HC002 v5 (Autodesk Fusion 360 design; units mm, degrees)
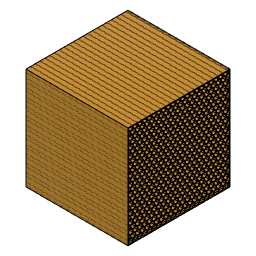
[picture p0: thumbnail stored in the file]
sketch "Sketch1" plane through (0, 0, 0) normal (1, 0, 0) x axis (0, 0, -1)
  line L1 (-75, 75) -> (75, 75)
  line L2 (-75, -75) -> (-75, 75)
  line L3 (75, -75) -> (-75, -75)
  line L4 (75, 75) -> (75, -75)
  line L5 (-75, -75) -> (75, 75)
  line L6 (75, -75) -> (-75, 75)
  line L7 (-71.3532, -71.3532) -> (0, 0)
  line L8 (-68.3532, -69.6211) -> (-68.3532, -73.0852)
  line L9 (-71.3532, -67.8891) -> (-68.3532, -69.6211)
  line L10 (-74, -69.4172) -> (-71.3532, -67.8891)
  line L11 (-72.7687, -74) -> (-74, -73.2891)
  line L12 (-68.3532, -73.0852) -> (-69.9376, -74)
  line L13 (-67.7706, -68.8181) -> (-70.7706, -67.0861)
  line L14 (-64.7706, -67.0861) -> (-67.7706, -68.8181)
  line L15 (-70.7706, -67.0861) -> (-70.7706, -63.622)
  line L16 (-64.7706, -63.622) -> (-64.7706, -67.0861)
  line L17 (-67.7706, -61.8899) -> (-64.7706, -63.622)
  line L18 (-70.7706, -63.622) -> (-67.7706, -61.8899)
  line L19 (-71.3532, -79.3958) -> (-71.3532, -71.3532)
  line L20 (-67.3532, -73.0852) -> (-67.3532, -69.6211)
  line L21 (-65.7687, -74) -> (-67.3532, -73.0852)
  line L22 (-61.3532, -73.0852) -> (-62.9376, -74)
  line L23 (-61.3532, -69.6211) -> (-61.3532, -73.0852)
  line L24 (-64.3532, -67.8891) -> (-61.3532, -69.6211)
  line L25 (-67.3532, -69.6211) -> (-64.3532, -67.8891)
  line L26 (-57.7706, -63.622) -> (-57.7706, -67.0861)
  line L27 (-60.7706, -61.8899) -> (-57.7706, -63.622)
  line L28 (-63.7706, -63.622) -> (-60.7706, -61.8899)
  line L29 (-63.7706, -67.0861) -> (-63.7706, -63.622)
  line L30 (-60.7706, -68.8181) -> (-63.7706, -67.0861)
  line L31 (-57.7706, -67.0861) -> (-60.7706, -68.8181)
  line L32 (-50.3532, -67.8891) -> (-47.3532, -69.6211)
  line L33 (-53.3532, -69.6211) -> (-50.3532, -67.8891)
  line L34 (-51.7687, -74) -> (-53.3532, -73.0852)
  line L35 (-47.3532, -73.0852) -> (-48.9376, -74)
  line L36 (-47.3532, -69.6211) -> (-47.3532, -73.0852)
  line L37 (-53.3532, -73.0852) -> (-53.3532, -69.6211)
  line L38 (-54.3532, -73.0852) -> (-55.9376, -74)
  line L39 (-57.3532, -67.8891) -> (-54.3532, -69.6211)
  line L40 (-60.3532, -69.6211) -> (-57.3532, -67.8891)
  line L41 (-58.7687, -74) -> (-60.3532, -73.0852)
  line L42 (-60.3532, -73.0852) -> (-60.3532, -69.6211)
  line L43 (-54.3532, -69.6211) -> (-54.3532, -73.0852)
  line L44 (-36.3532, -67.8891) -> (-33.3532, -69.6211)
  line L45 (-39.3532, -69.6211) -> (-36.3532, -67.8891)
  line L46 (-37.7687, -74) -> (-39.3532, -73.0852)
  line L47 (-33.3532, -73.0852) -> (-34.9376, -74)
  line L48 (-33.3532, -69.6211) -> (-33.3532, -73.0852)
  line L49 (-39.3532, -73.0852) -> (-39.3532, -69.6211)
  line L50 (-40.3532, -73.0852) -> (-41.9376, -74)
  line L51 (-43.3532, -67.8891) -> (-40.3532, -69.6211)
  line L52 (-46.3532, -69.6211) -> (-43.3532, -67.8891)
  line L53 (-44.7687, -74) -> (-46.3532, -73.0852)
  line L54 (-46.3532, -73.0852) -> (-46.3532, -69.6211)
  line L55 (-40.3532, -69.6211) -> (-40.3532, -73.0852)
  line L56 (-53.7706, -61.8899) -> (-50.7706, -63.622)
  line L57 (-56.7706, -63.622) -> (-53.7706, -61.8899)
  line L58 (-56.7706, -67.0861) -> (-56.7706, -63.622)
  line L59 (-53.7706, -68.8181) -> (-56.7706, -67.0861)
  line L60 (-50.7706, -67.0861) -> (-53.7706, -68.8181)
  line L61 (-50.7706, -63.622) -> (-50.7706, -67.0861)
  line L62 (-49.7706, -67.0861) -> (-49.7706, -63.622)
  line L63 (-46.7706, -68.8181) -> (-49.7706, -67.0861)
  line L64 (-43.7706, -67.0861) -> (-46.7706, -68.8181)
  line L65 (-43.7706, -63.622) -> (-43.7706, -67.0861)
  line L66 (-46.7706, -61.8899) -> (-43.7706, -63.622)
  line L67 (-49.7706, -63.622) -> (-46.7706, -61.8899)
  line L68 (-39.7706, -61.8899) -> (-36.7706, -63.622)
  line L69 (-42.7706, -63.622) -> (-39.7706, -61.8899)
  line L70 (-42.7706, -67.0861) -> (-42.7706, -63.622)
  line L71 (-39.7706, -68.8181) -> (-42.7706, -67.0861)
  line L72 (-36.7706, -67.0861) -> (-39.7706, -68.8181)
  line L73 (-36.7706, -63.622) -> (-36.7706, -67.0861)
  line L74 (-35.7706, -67.0861) -> (-35.7706, -63.622)
  line L75 (-32.7706, -68.8181) -> (-35.7706, -67.0861)
  line L76 (-29.7706, -67.0861) -> (-32.7706, -68.8181)
  line L77 (-29.7706, -63.622) -> (-29.7706, -67.0861)
  line L78 (-32.7706, -61.8899) -> (-29.7706, -63.622)
  line L79 (-35.7706, -63.622) -> (-32.7706, -61.8899)
  line L80 (9.2294, -61.8899) -> (12.2294, -63.622)
  line L81 (12.2294, -63.622) -> (12.2294, -67.0861)
  line L82 (-0.7706, -63.622) -> (2.2294, -61.8899)
  line L83 (2.6468, -73.0852) -> (2.6468, -69.6211)
  line L84 (-4.3532, -69.6211) -> (-1.3532, -67.8891)
  line L85 (1.6468, -69.6211) -> (1.6468, -73.0852)
  line L86 (-14.7706, -63.622) -> (-11.7706, -61.8899)
  line L87 (-25.7706, -61.8899) -> (-22.7706, -63.622)
  line L88 (-5.3532, -73.0852) -> (-6.9376, -74)
  line L89 (-2.7687, -74) -> (-4.3532, -73.0852)
  line L90 (-7.7706, -63.622) -> (-4.7706, -61.8899)
  line L91 (-0.7706, -67.0861) -> (-0.7706, -63.622)
  line L92 (5.2294, -67.0861) -> (2.2294, -68.8181)
  line L93 (-8.3532, -67.8891) -> (-5.3532, -69.6211)
  line L94 (2.2294, -68.8181) -> (-0.7706, -67.0861)
  line L95 (2.6468, -69.6211) -> (5.6468, -67.8891)
  line L96 (-4.7706, -61.8899) -> (-1.7706, -63.622)
  line L97 (8.6468, -69.6211) -> (8.6468, -73.0852)
  line L98 (-21.7706, -63.622) -> (-18.7706, -61.8899)
  line L99 (1.6468, -73.0852) -> (0.0624, -74)
  line L100 (-7.7706, -67.0861) -> (-7.7706, -63.622)
  line L101 (-18.7706, -61.8899) -> (-15.7706, -63.622)
  line L102 (5.2294, -63.622) -> (5.2294, -67.0861)
  line L103 (4.2313, -74) -> (2.6468, -73.0852)
  line L104 (-28.7706, -63.622) -> (-25.7706, -61.8899)
  line L105 (2.2294, -61.8899) -> (5.2294, -63.622)
  line L106 (6.2294, -63.622) -> (9.2294, -61.8899)
  line L107 (-11.7706, -61.8899) -> (-8.7706, -63.622)
  line L108 (12.2294, -67.0861) -> (9.2294, -68.8181)
  line L109 (-1.3532, -67.8891) -> (1.6468, -69.6211)
  line L110 (-8.7706, -67.0861) -> (-11.7706, -68.8181)
  line L111 (-11.3532, -69.6211) -> (-8.3532, -67.8891)
  line L112 (-9.7687, -74) -> (-11.3532, -73.0852)
  line L113 (-1.7706, -63.622) -> (-1.7706, -67.0861)
  line L114 (8.6468, -73.0852) -> (7.0624, -74)
  line L115 (-1.7706, -67.0861) -> (-4.7706, -68.8181)
  line L116 (5.6468, -67.8891) -> (8.6468, -69.6211)
  line L117 (-4.7706, -68.8181) -> (-7.7706, -67.0861)
  line L118 (-11.7706, -68.8181) -> (-14.7706, -67.0861)
  line L119 (6.2294, -67.0861) -> (6.2294, -63.622)
  line L120 (-8.7706, -63.622) -> (-8.7706, -67.0861)
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  point P6 (0, 0)
  point P1 (0, 0)
  point P7 (0, 0)
  point P8 (-71.3532, -71.3532)
  point P12 (-71.3532, -71.3532)
  point P3957 (0, 0)
  point P3958 (-75, 21.9776)
  point P3971 (-75, 45.9776)
  point P3981 (-74.3532, 74.3532)
  point P3982 (-75, 63.3143)
  point P3998 (75, 56.5105)
  point P4 (-75, -75)
  point P5 (75, -75)
  point P3 (-75, 75)
  point P15 (-67.8532, -65.291)
  point P26 (-64.3532, -71.3532)
  point P3955 (-74, -74)
  point P3956 (74, -74)
  point P3954 (-74, 74)
  horizontal L1
  perpendicular L1 L2
  parallel L1 L3
  parallel L2 L4
  coincident L5 P6
  coincident L6 P6
  coincident P1 P6
  coincident P6 P7
  vertical L8
  coincident P8 P12
  vertical L19
  coincident P6 P3957
  coincident L2 P3958
  coincident L2 P3971
  coincident L6 P3981
  coincident L2 P3982
  coincident L4 P3998
  dimension "d1" distance P4 P5 = 150
  dimension "d2" distance P3 P4 = 150
  dimension "d10" distance P12 P15 = 7
  dimension "d15" distance P15 P26 = 7
  dimension "d56" distance P3955 P3956 = 148
  dimension "d57" distance P3954 P3955 = 148
  dimension "d58" distance P12 L8 = 3
  dimension "d18" R-Pattern2-uDistance = 7
  dimension "d19" R-Pattern2-vDistance = 0
  dimension "d26" R-Pattern4-uDistance = 14
  dimension "d27" R-Pattern4-vDistance = 0
extrude "Extrude1" new body sketch "Sketch1" along normal blind 150
sketch "Sketch2" plane through (150, 0, 0) normal (1, 0, 0) x axis (0, 0, -1)
  line L1 (9.2294, -44.8181) -> (12.2294, -43.0861)
  line L2 (6.2294, -43.0861) -> (9.2294, -44.8181)
  line L3 (6.2294, -39.622) -> (6.2294, -43.0861)
  line L4 (9.2294, -37.8899) -> (6.2294, -39.622)
  line L5 (12.2294, -39.622) -> (9.2294, -37.8899)
  line L6 (12.2294, -43.0861) -> (12.2294, -39.622)
  line L7 (-49.7706, 32.378) -> (-49.7706, 28.9139)
  line L8 (-46.7706, 34.1101) -> (-49.7706, 32.378)
  line L9 (-43.7706, 32.378) -> (-46.7706, 34.1101)
  line L10 (-43.7706, 28.9139) -> (-43.7706, 32.378)
  line L11 (-46.7706, 27.1819) -> (-43.7706, 28.9139)
  line L12 (-49.7706, 28.9139) -> (-46.7706, 27.1819)
  line L13 (-50.7706, 28.9139) -> (-50.7706, 32.378)
  line L14 (-53.7706, 27.1819) -> (-50.7706, 28.9139)
  line L15 (-56.7706, 28.9139) -> (-53.7706, 27.1819)
  line L16 (-56.7706, 32.378) -> (-56.7706, 28.9139)
  line L17 (-53.7706, 34.1101) -> (-56.7706, 32.378)
  line L18 (-50.7706, 32.378) -> (-53.7706, 34.1101)
  line L19 (13.2294, 32.378) -> (13.2294, 28.9139)
  line L20 (16.2294, 34.1101) -> (13.2294, 32.378)
  line L21 (19.2294, 32.378) -> (16.2294, 34.1101)
  line L22 (19.2294, 28.9139) -> (19.2294, 32.378)
  line L23 (16.2294, 27.1819) -> (19.2294, 28.9139)
  line L24 (13.2294, 28.9139) -> (16.2294, 27.1819)
  line L25 (-25.3532, 58.9148) -> (-22.3532, 57.1827)
  line L26 (-25.3532, 62.3789) -> (-25.3532, 58.9148)
  line L27 (-22.3532, 64.1109) -> (-25.3532, 62.3789)
  line L28 (-19.3532, 62.3789) -> (-22.3532, 64.1109)
  line L29 (-19.3532, 58.9148) -> (-19.3532, 62.3789)
  line L30 (-22.3532, 57.1827) -> (-19.3532, 58.9148)
  line L31 (27.2294, 32.378) -> (27.2294, 28.9139)
  line L32 (30.2294, 34.1101) -> (27.2294, 32.378)
  line L33 (33.2294, 32.378) -> (30.2294, 34.1101)
  line L34 (33.2294, 28.9139) -> (33.2294, 32.378)
  line L35 (30.2294, 27.1819) -> (33.2294, 28.9139)
  line L36 (27.2294, 28.9139) -> (30.2294, 27.1819)
  line L37 (12.6468, 21.1827) -> (15.6468, 22.9148)
  line L38 (9.6468, 22.9148) -> (12.6468, 21.1827)
  line L39 (9.6468, 26.3789) -> (9.6468, 22.9148)
  line L40 (12.6468, 28.1109) -> (9.6468, 26.3789)
  line L41 (15.6468, 26.3789) -> (12.6468, 28.1109)
  line L42 (15.6468, 22.9148) -> (15.6468, 26.3789)
  line L43 (16.6468, 26.3789) -> (16.6468, 22.9148)
  line L44 (19.6468, 28.1109) -> (16.6468, 26.3789)
  line L45 (22.6468, 26.3789) -> (19.6468, 28.1109)
  line L46 (22.6468, 22.9148) -> (22.6468, 26.3789)
  line L47 (19.6468, 21.1827) -> (22.6468, 22.9148)
  line L48 (16.6468, 22.9148) -> (19.6468, 21.1827)
  line L49 (29.6468, 26.3789) -> (26.6468, 28.1109)
  line L50 (29.6468, 22.9148) -> (29.6468, 26.3789)
  line L51 (26.6468, 21.1827) -> (29.6468, 22.9148)
  line L52 (23.6468, 22.9148) -> (26.6468, 21.1827)
  line L53 (23.6468, 26.3789) -> (23.6468, 22.9148)
  line L54 (26.6468, 28.1109) -> (23.6468, 26.3789)
  line L55 (20.2294, 32.378) -> (20.2294, 28.9139)
  line L56 (23.2294, 34.1101) -> (20.2294, 32.378)
  line L57 (26.2294, 32.378) -> (23.2294, 34.1101)
  line L58 (26.2294, 28.9139) -> (26.2294, 32.378)
  line L59 (23.2294, 27.1819) -> (26.2294, 28.9139)
  line L60 (20.2294, 28.9139) -> (23.2294, 27.1819)
  line L61 (9.2294, 27.1819) -> (12.2294, 28.9139)
  line L62 (6.2294, 28.9139) -> (9.2294, 27.1819)
  line L63 (6.2294, 32.378) -> (6.2294, 28.9139)
  line L64 (9.2294, 34.1101) -> (6.2294, 32.378)
  line L65 (12.2294, 32.378) -> (9.2294, 34.1101)
  line L66 (12.2294, 28.9139) -> (12.2294, 32.378)
  line L67 (-61.3532, 26.3789) -> (-64.3532, 28.1109)
  line L68 (-61.3532, 22.9148) -> (-61.3532, 26.3789)
  line L69 (-64.3532, 21.1827) -> (-61.3532, 22.9148)
  line L70 (-67.3532, 22.9148) -> (-64.3532, 21.1827)
  line L71 (-67.3532, 26.3789) -> (-67.3532, 22.9148)
  line L72 (-64.3532, 28.1109) -> (-67.3532, 26.3789)
  line L73 (5.2294, 32.378) -> (2.2294, 34.1101)
  line L74 (5.2294, 28.9139) -> (5.2294, 32.378)
  line L75 (2.2294, 27.1819) -> (5.2294, 28.9139)
  line L76 (-0.7706, 28.9139) -> (2.2294, 27.1819)
  line L77 (-0.7706, 32.378) -> (-0.7706, 28.9139)
  line L78 (2.2294, 34.1101) -> (-0.7706, 32.378)
  line L79 (-15.7706, 32.378) -> (-18.7706, 34.1101)
  line L80 (-15.7706, 28.9139) -> (-15.7706, 32.378)
  line L81 (-18.7706, 27.1819) -> (-15.7706, 28.9139)
  line L82 (-21.7706, 28.9139) -> (-18.7706, 27.1819)
  line L83 (-21.7706, 32.378) -> (-21.7706, 28.9139)
  line L84 (-18.7706, 34.1101) -> (-21.7706, 32.378)
  line L85 (-4.7706, 34.1101) -> (-7.7706, 32.378)
  line L86 (-1.7706, 32.378) -> (-4.7706, 34.1101)
  line L87 (-1.7706, 28.9139) -> (-1.7706, 32.378)
  line L88 (-4.7706, 27.1819) -> (-1.7706, 28.9139)
  line L89 (-7.7706, 28.9139) -> (-4.7706, 27.1819)
  line L90 (-7.7706, 32.378) -> (-7.7706, 28.9139)
  line L91 (54.2294, 28.9139) -> (54.2294, 32.378)
  line L92 (51.2294, 27.1819) -> (54.2294, 28.9139)
  line L93 (48.2294, 28.9139) -> (51.2294, 27.1819)
  line L94 (48.2294, 32.378) -> (48.2294, 28.9139)
  line L95 (51.2294, 34.1101) -> (48.2294, 32.378)
  line L96 (54.2294, 32.378) -> (51.2294, 34.1101)
  line L97 (-4.7706, 22.1101) -> (-7.7706, 20.378)
  line L98 (-1.7706, 20.378) -> (-4.7706, 22.1101)
  line L99 (-1.7706, 16.9139) -> (-1.7706, 20.378)
  line L100 (-4.7706, 15.1819) -> (-1.7706, 16.9139)
  line L101 (-7.7706, 16.9139) -> (-4.7706, 15.1819)
  line L102 (-7.7706, 20.378) -> (-7.7706, 16.9139)
  line L103 (-8.3532, 64.1109) -> (-11.3532, 62.3789)
  line L104 (-5.3532, 62.3789) -> (-8.3532, 64.1109)
  line L105 (-5.3532, 58.9148) -> (-5.3532, 62.3789)
  line L106 (-8.3532, 57.1827) -> (-5.3532, 58.9148)
  line L107 (-11.3532, 58.9148) -> (-8.3532, 57.1827)
  line L108 (-11.3532, 62.3789) -> (-11.3532, 58.9148)
  line L109 (74, 10.1335) -> (74, 15.1601)
  line L110 (72.6468, 10.9148) -> (74, 10.1335)
  line L111 (72.6468, 14.3789) -> (72.6468, 10.9148)
  line L112 (74, 15.1601) -> (72.6468, 14.3789)
  line L113 (-35.7706, 68.378) -> (-35.7706, 64.9139)
  line L114 (-32.7706, 70.1101) -> (-35.7706, 68.378)
  line L115 (-29.7706, 68.378) -> (-32.7706, 70.1101)
  line L116 (-29.7706, 64.9139) -> (-29.7706, 68.378)
  line L117 (-32.7706, 63.1819) -> (-29.7706, 64.9139)
  line L118 (-35.7706, 64.9139) -> (-32.7706, 63.1819)
  line L119 (13.2294, 68.378) -> (13.2294, 64.9139)
  line L120 (16.2294, 70.1101) -> (13.2294, 68.378)
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  point P1904 (-28.7706, 8.378)
  point P3256 (-28.7706, 8.378)
  point P1905 (-25.7706, 10.1101)
  point P3257 (-25.7706, 10.1101)
  point P1906 (-22.7706, 8.378)
  point P3258 (-22.7706, 8.378)
  point P1907 (-22.7706, 4.9139)
  point P3259 (-22.7706, 4.9139)
  point P1908 (-25.7706, 3.1819)
  point P3260 (-25.7706, 3.1819)
  point P1909 (-28.7706, 4.9139)
  point P3261 (-28.7706, 4.9139)
  point P3262 (-28.7706, 4.9139)
  point P1429 (-25.7706, -13.8899)
  point P3263 (-25.7706, -13.8899)
  point P1430 (-22.7706, -15.622)
  point P3264 (-22.7706, -15.622)
  point P3265 (-22.7706, -15.622)
  point P1431 (-22.7706, -19.0861)
  point P3266 (-22.7706, -19.0861)
  point P3267 (-22.7706, -19.0861)
  point P1432 (-25.7706, -20.8181)
  point P3268 (-25.7706, -20.8181)
  point P1433 (-28.7706, -19.0861)
  point P3269 (-28.7706, -19.0861)
  point P1428 (-28.7706, -15.622)
  point P3270 (-28.7706, -15.622)
  coincident P1904 P3256
  coincident P1905 P3257
  coincident P1906 P3258
  coincident P1907 P3259
  coincident P1908 P3260
  coincident P1909 P3261
  coincident P1909 P3262
  coincident P1429 P3263
  coincident P1430 P3264
  coincident P1430 P3265
  coincident P1431 P3266
  coincident P1431 P3267
  coincident P1432 P3268
  coincident P1433 P3269
  coincident P1428 P3270
  dimension "d61" diameter = 23.5
extrude "Extrude2" new body sketch "Sketch2" along normal blind 20
sketch "Sketch3" plane through (170, 0, 0) normal (1, 0, 0) x axis (0, 0, -1)
  line L1 (-21.7706, -7.0861) -> (-21.7706, -3.622)
  line L2 (-18.7706, -8.8181) -> (-21.7706, -7.0861)
  line L3 (-15.7706, -7.0861) -> (-18.7706, -8.8181)
  line L4 (-15.7706, -3.622) -> (-15.7706, -7.0861)
  line L5 (-18.7706, -1.8899) -> (-15.7706, -3.622)
  line L6 (-21.7706, -3.622) -> (-18.7706, -1.8899)
  line L7 (-28.7706, 4.9139) -> (-28.7706, 8.378)
  line L8 (-25.7706, 3.1819) -> (-28.7706, 4.9139)
  line L9 (-22.7706, 4.9139) -> (-25.7706, 3.1819)
  line L10 (-22.7706, 8.378) -> (-22.7706, 4.9139)
  line L11 (-25.7706, 10.1101) -> (-22.7706, 8.378)
  line L12 (-28.7706, 8.378) -> (-25.7706, 10.1101)
  line L13 (-29.7706, -7.0861) -> (-32.7706, -8.8181)
  line L14 (-29.7706, -3.622) -> (-29.7706, -7.0861)
  line L15 (-32.7706, -1.8899) -> (-29.7706, -3.622)
  line L16 (-35.7706, -3.622) -> (-32.7706, -1.8899)
  line L17 (-35.7706, -7.0861) -> (-35.7706, -3.622)
  line L18 (-32.7706, -8.8181) -> (-35.7706, -7.0861)
  line L19 (-25.7706, -13.8899) -> (-22.7706, -15.622)
  line L20 (-28.7706, -15.622) -> (-25.7706, -13.8899)
  line L21 (-28.7706, -19.0861) -> (-28.7706, -15.622)
  line L22 (-25.7706, -20.8181) -> (-28.7706, -19.0861)
  line L23 (-22.7706, -19.0861) -> (-25.7706, -20.8181)
  line L24 (-22.7706, -15.622) -> (-22.7706, -19.0861)
  line L25 (-15.7706, -5.354) -> (-35.7706, -5.354)
  line L26 (-25.7706, -13.8899) -> (-25.7706, 3.1819)
  circle C1 centre (-25.7706, -5.354) radius 12
  circle C2 centre (-25.7706, -5.354) radius 16
  circle C3 centre (-25.7706, -5.354) radius 4
  point P26 (-35.7706, -5.354)
  point P27 (-15.7706, -5.354)
  point P10 (-25.7706, 3.1819)
  point P28 (-25.7706, 3.1819)
  point P21 (-25.7706, -13.8899)
  point P29 (-25.7706, -13.8899)
  point P30 (-25.7706, -5.354)
  midpoint L17 P26
  midpoint L4 P27
  coincident P10 P28
  coincident P21 P29
  midpoint L25 P30
  concentric C1 C2
  concentric C1 C3
  tangent L14 C3
  dimension "d64" diameter C1 = 24
  dimension "d65" diameter C2 = 32
extrude "Extrude3" add sketch "Sketch3" profile of L1 L2 L3 L4 L5 L6 L7 L8 L9 L10 L11 L12 L13 L14 L15 L16 L17 L18 L19 L20 L21 L22 L23 L24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 along normal blind 8
sketch "Sketch4" plane through (178, 0, 0) normal (1, 0, 0) x axis (0, 0, -1)
  circle C1 centre (-25.7706, -5.354) radius 4
  circle C2 centre (-25.7706, -5.354) radius 16
  circle C3 centre (-25.7706, -5.354) radius 12
  concentric C1 C3
  dimension "d68" diameter C3 = 24
extrude "Extrude4" cut sketch "Sketch4" profile of C1 C3 against normal blind 6.5
fillet "Fillet1" radius 1 0.8
fillet "Fillet2" radius 0.5
fillet "Fillet3" radius 0.5
sketch "Sketch5" plane through (178, 0, 0) normal (1, 0, 0) x axis (0, 0, -1)
  line L1 (-25.7706, 9.846) -> (-25.7706, -5.354)
  line L2 (-24.2706, 6.146) -> (-27.2706, 6.146)
  line L3 (-24.2706, 11.146) -> (-24.2706, 6.146)
  line L4 (-27.2706, 11.146) -> (-24.2706, 11.146)
  line L5 (-27.2706, 6.146) -> (-27.2706, 11.146)
  circle C1 centre (-25.7706, -5.354) radius 13
  circle C2 centre (-25.7706, -5.354) radius 15.2
  point P2 (-25.7706, -5.354)
  point P3 (-25.7706, -5.354)
  point P4 (-25.7706, 9.846)
  point P5 (-27.2706, 6.146)
  point P8 (-27.2706, 11.146)
  point P6 (-24.2706, 6.146)
  coincident P2 P3
  coincident C2 P4
  vertical L1
  horizontal L2
  vertical L3
  horizontal L4
  vertical L5
  symmetric L1 L3 L5
  dimension "d79" distance P5 P8 = 5
  dimension "d80" distance P5 P6 = 3
  dimension "d81" distance P3 P6 = 11.5
extrude "Extrude5" cut sketch "Sketch5" profile of C1 C2 L2 L3 L4 L5 against normal blind 5
fillet "Fillet4" radius 0.5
